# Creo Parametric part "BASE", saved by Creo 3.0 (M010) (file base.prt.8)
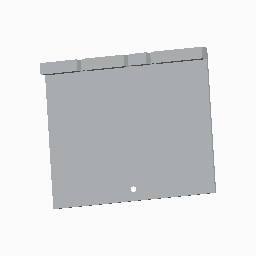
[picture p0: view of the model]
Units: millimeter Kilogram Sec (mmKs); MM, KILOGRAM, SECS

Created from: SOLID_PART_MMKS.PRT

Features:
  1. coordinate system
  2. datum plane "RIGHT"
  3. datum plane "TOP"
  4. datum plane "FRONT"
  5. sketch "Sketch 1"
  6. extrusion "Extrude 1"
  7. sketch "Sketch 2"
  8. extrusion "Extrude 2"
  9. extrusion "Extrude 3"
  10. extruded cut "Extrude 4"

Surfaces: 18 plane, 2 cylinder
